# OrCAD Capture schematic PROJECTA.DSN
size A; title: Boost Converter; rev: 1
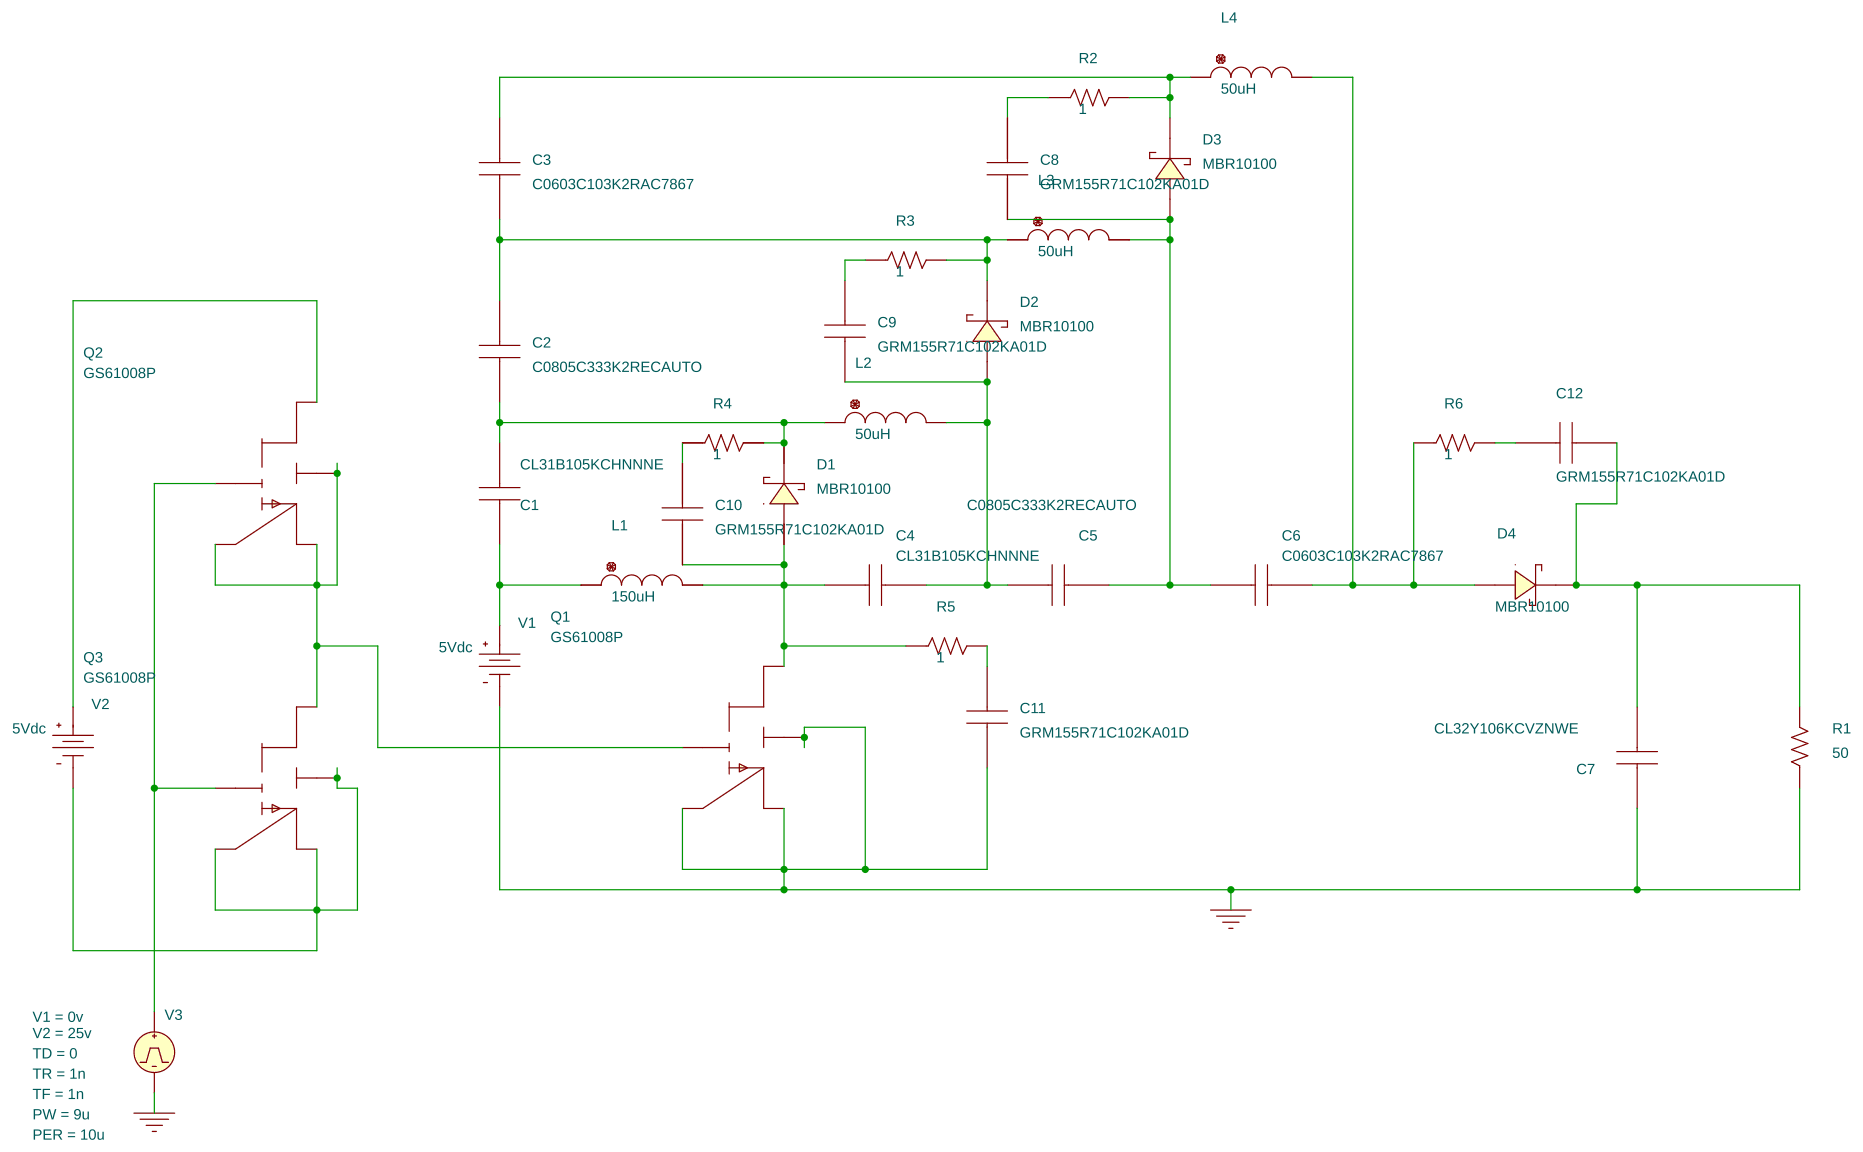
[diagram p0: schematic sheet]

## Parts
C1  CL31B105KCHNNNE  [CAPC3216X180N]
C2  C0805C333K2RECAUTO  [C0805]
C3  C0603C103K2RAC7867  [CAPC1608X87N]
C4  CL31B105KCHNNNE  [CAPC3216X180N]
C5  C0805C333K2RECAUTO  [C0805]
C6  C0603C103K2RAC7867  [CAPC1608X87N]
C7  CL32Y106KCVZNWE  [CAPC3225X280N]
C8  GRM155R71C102KA01D  [CAPC1005X55N]
C9  GRM155R71C102KA01D  [CAPC1005X55N]
C10  GRM155R71C102KA01D  [CAPC1005X55N]
C11  GRM155R71C102KA01D  [CAPC1005X55N]
C12  GRM155R71C102KA01D  [CAPC1005X55N]
D1  MBR10100  [to220ac]
D2  MBR10100  [to220ac]
D3  MBR10100  [to220ac]
D4  MBR10100  [to220ac]
L1  150uH  [DISC350x175LS200x100034]
L2  50uH  [DISC350x175LS200x100034]
L3  50uH  [DISC350x175LS200x100034]
L4  50uH  [DISC350x175LS200x100034]
Q1  GS61008P  [GS61008P]
Q2  GS61008P  [GS61008P]
Q3  GS61008P  [GS61008P]
R1  50  [AXRC05]
R2  1  [AXRC05]
R3  1  [AXRC05]
R4  1  [AXRC05]
R5  1  [AXRC05]
R6  1  [AXRC05]
V1  VDC
V2  VDC
V3  VPULSE

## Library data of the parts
C1 C4 = CL31B105KCHNNNE: Manufacturer Name: SAMSUNG; Source Id: SamacSys
C2 C5 = C0805C333K2RECAUTO: Manufacturer Name: KEMET; Source Id: SamacSys
C3 C6 = C0603C103K2RAC7867: Manufacturer Name: KEMET; Source Id: SamacSys
C7 = CL32Y106KCVZNWE: Manufacturer Name: SAMSUNG; Source Id: SamacSys
C8-C12 = GRM155R71C102KA01D: Manufacturer Name: Murata Electronics; Source Id: SamacSys
D1-D4 = MBR10100
L1-L4 = L
Q1 = GS61008P: Manufacturer Name: GaN Systems; Source Id: SamacSys
Q2 Q3 = GS61008P
R1-R6 = R
V1 V2 = VDC: DC: 5Vdc
V3 = VPULSE: PER: 10u; PW: 9u; TD: 0; TF: 1n; TR: 1n; V1: 0v; V2: 25v

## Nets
0: C7.1 C11.1 Q1.3(SS) Q1.4(S) Q1.5(EP) R1.1 V1.1(-) V3.2(-)
N9027527: C1.1 L1.1 V1.0(+)
N9027674: C2.2 C3.1 D2.1(C) L3.1 R3.2
N9027678: C1.2 C2.1 D1.1(C) L2.1 R4.2
N9027682: C4.1 C10.1 D1.3(A) L1.2 Q1.1(D) R5.1
N9027781: C4.2 C5.1 C9.1 D2.3(A) L2.2
N9027869: C5.2 C6.1 C8.1 D3.3(A) L3.2
N9027907: C3.2 D3.1(C) L4.1 R2.2
N9028039: C6.2 D4.3(A) L4.2 R6.1
N9028541: C7.2 C12.1 D4.1(C) R1.2
N9028925: Q1.2(G) Q2.3(SS) Q2.4(S) Q2.5(EP) Q3.1(D)
N9028952: Q3.3(SS) Q3.4(S) Q3.5(EP) V2.1(-)
N9029116: Q2.1(D) V2.0(+)
N9029265: Q2.2(G) Q3.2(G) V3.1(+)
N9029780: C8.2 R2.1
N9029826: C9.2 R3.1
N9029858: C10.2 R4.1
N9029875: C12.2 R6.2
N9029928: C11.2 R5.2

Not connected (* = marked no-connect by the designer): D1 4(C1); D2 4(C1); D3 4(C1); D4 4(C1)
